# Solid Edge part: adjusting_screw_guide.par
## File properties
Title: Adjusting screw guide
Author: Robert a Rhodes jr
Template: Normal.par
Last saved by: Rajat Kamboj
Revision: 18
Application: Solid Edge
Accuracy: 0.99
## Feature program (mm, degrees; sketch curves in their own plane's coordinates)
sketch for "unnamed Protrusion 1" plane through (0, 0, 0) normal (0, -1, 0) x-axis (1, 0, 0)
  circle centre (0, 0) radius 7.9375
extrude "unnamed Protrusion 1" add finite 63.5 along +normal
sketch for "ExtrudedProtrusion_2" plane through (0, -63.5, 0) normal (0, -1, 0) x-axis (1, 0, 0)
  circle centre (0, 0) radius 6.3119
extrude "ExtrudedProtrusion_2" add finite 76.2 along +normal
chamfer "Chamfer_1" setback 1.5748
sketch for "ExtrudedCutout_1" plane through (0, 0, 0) normal (0, 0, 1) x-axis (1, 0, 0)
  line (1.1811, 0) -> (1.1811, -4.7498)
  line (1.1811, -4.7498) -> (-1.1811, -4.7498)
  line (-1.1811, -4.7498) -> (-1.1811, 0)
  line (-1.1811, 0) -> (1.1811, 0)
extrude "ExtrudedCutout_1" cut finite 101.6 symmetric
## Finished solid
Body 1: solid body, 10 faces, 16 edges, 8 vertices.
  Faces by surface: plane 7, cylinder 2, cone 1
  Edges by curve: circle 8, line 8
Bounding box of the edges (mm): 15.875 x 139.700 x 15.875, from (-7.9375, -139.7, -7.9375) to (7.9375, 0, 7.9375).
Cylindrical faces by radius (mm): R6.3119 x1, R7.9375 x1
Conical faces (half-angle, radius in mm at the cone's reference point): 45 deg R6.3119 x1
Planar faces by outward normal: +x 1, +y 3, -x 1, -y 2
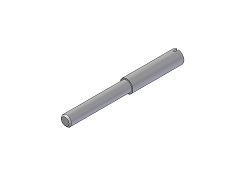
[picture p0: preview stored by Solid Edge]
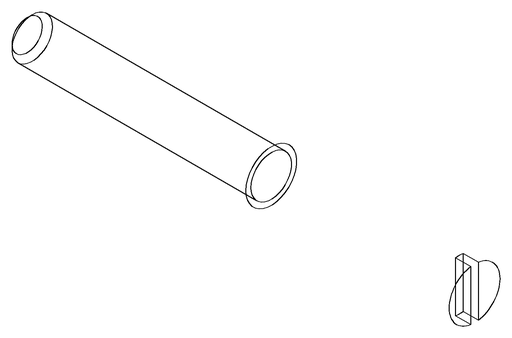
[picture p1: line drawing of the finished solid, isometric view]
